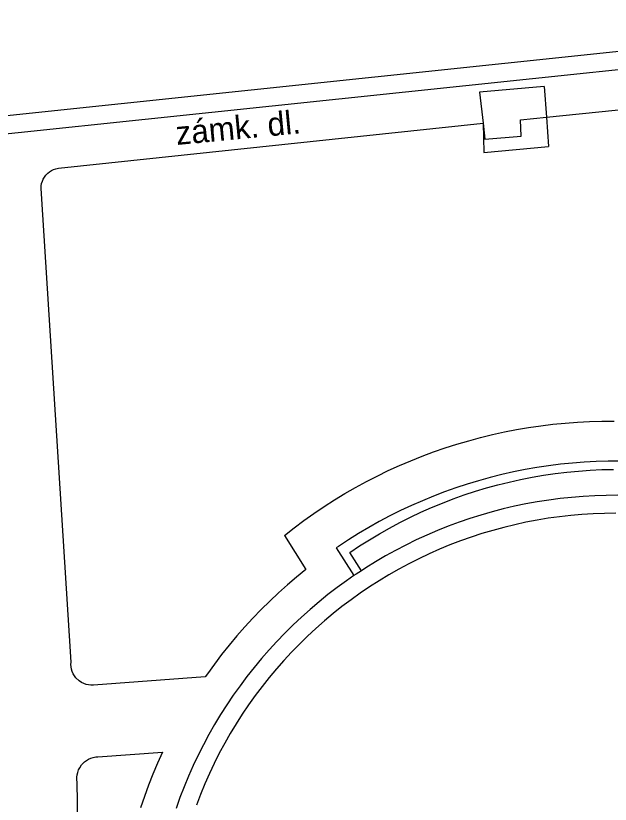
# Model space of a CAD drawing. Extents: x -539515 to -538098, y -1182060 to -1180157.
# Drawn here: x -539326.9 to -539310.4, y -1181191.92 to -1181170.02 of the extents above; entities that cross this region are included whole.
import ezdxf

# ---------------------------------------------------------------- set-up
doc = ezdxf.new("R2010")
doc.units = 0
for name, color, linetype in [('Vrstva 11', 7, 'Continuous'), ('Vrstva 40', 7, 'Continuous'), ('Vrstva 5', 7, 'Continuous')]:
    doc.layers.add(name, color=color, linetype=linetype)

msp = doc.modelspace()

# ---------------------------------------------------------------- linework, layer by layer
at = {"layer": 'Vrstva 11'}
for p, q in [((-539312.23, -1181171.98), (-539314.02, -1181172.14)), ((-539312.23, -1181171.98), (-539312.168, -1181172.836)), ((-539312.87, -1181173.36), (-539312.89, -1181172.91)), ((-539312.168, -1181172.836), (-539312.11, -1181173.65)), ((-539325.71, -1181174.25), (-539313.92, -1181173)), ((-539313.88, -1181173.44), (-539312.87, -1181173.36)), ((-539313.9, -1181173.81), (-539312.11, -1181173.65)), ((-539325.36, -1181187.97), (-539326.19, -1181174.81)), ((-539319.44, -1181184.45), (-539318.844, -1181185.399)), ((-539318, -1181184.8), (-539317.51, -1181185.57)), ((-539317.302, -1181185.432), (-539317.623, -1181184.926)), ((-539321.635, -1181188.38), (-539324.74, -1181188.61)), ((-539324.62, -1181190.6), (-539322.827, -1181190.472)), ((-539325.16, -1181193.67), (-539325.19, -1181191.31))]:
    msp.add_line(p, q, dxfattribs=at)
for points in [[(-539312.168, -1181172.836), (-539303.54, -1181171.95)], [(-539314.02, -1181172.14), (-539313.92, -1181173), (-539313.9, -1181173.81)], [(-539312.89, -1181172.91), (-539312.168, -1181172.836)], [(-539313.92, -1181173), (-539313.88, -1181173.44)], [(-539326.19, -1181174.81), (-539326.187, -1181174.744), (-539326.177, -1181174.678), (-539326.158, -1181174.614), (-539326.133, -1181174.553), (-539326.099, -1181174.495), (-539326.06, -1181174.442), (-539326.01, -1181174.39), (-539325.962, -1181174.351), (-539325.906, -1181174.315), (-539325.847, -1181174.286), (-539325.784, -1181174.265), (-539325.71, -1181174.25)], [(-539319.44, -1181184.45), (-539319.172, -1181184.24), (-539318.898, -1181184.037), (-539318.62, -1181183.841), (-539318.338, -1181183.65), (-539318.051, -1181183.467), (-539317.759, -1181183.29), (-539317.464, -1181183.121), (-539317.165, -1181182.958), (-539316.862, -1181182.802), (-539316.556, -1181182.653), (-539316.246, -1181182.512), (-539315.933, -1181182.378), (-539315.617, -1181182.252), (-539315.298, -1181182.132), (-539314.976, -1181182.021), (-539314.651, -1181181.917), (-539314.325, -1181181.82), (-539313.996, -1181181.732), (-539313.665, -1181181.651), (-539313.333, -1181181.578), (-539312.998, -1181181.512), (-539312.663, -1181181.455), (-539312.326, -1181181.405), (-539311.988, -1181181.364), (-539311.649, -1181181.33), (-539311.309, -1181181.304), (-539310.969, -1181181.287), (-539310.629, -1181181.277), (-539310.288, -1181181.275)], [(-539310.121, -1181182.386), (-539310.453, -1181182.388), (-539310.785, -1181182.397), (-539311.116, -1181182.415), (-539311.447, -1181182.441), (-539311.776, -1181182.474), (-539312.106, -1181182.516), (-539312.434, -1181182.566), (-539312.76, -1181182.623), (-539313.085, -1181182.688), (-539313.409, -1181182.761), (-539313.731, -1181182.842), (-539314.05, -1181182.931), (-539314.368, -1181183.027), (-539314.683, -1181183.131), (-539314.995, -1181183.242)], [(-539317.623, -1181184.926), (-539317.353, -1181184.746), (-539317.079, -1181184.572), (-539316.801, -1181184.405), (-539316.519, -1181184.246), (-539316.233, -1181184.093), (-539315.943, -1181183.947), (-539315.65, -1181183.808), (-539315.353, -1181183.677), (-539315.054, -1181183.553), (-539314.751, -1181183.437), (-539314.446, -1181183.328), (-539314.138, -1181183.226), (-539313.827, -1181183.133), (-539313.514, -1181183.046), (-539313.2, -1181182.968), (-539312.883, -1181182.897), (-539312.565, -1181182.835), (-539312.245, -1181182.78), (-539311.924, -1181182.733), (-539311.602, -1181182.694), (-539311.28, -1181182.663), (-539310.956, -1181182.639), (-539310.632, -1181182.624), (-539310.308, -1181182.617)], [(-539314.995, -1181183.242), (-539315.305, -1181183.361), (-539315.611, -1181183.488), (-539315.915, -1181183.622), (-539316.215, -1181183.763), (-539316.512, -1181183.911), (-539316.805, -1181184.066), (-539317.094, -1181184.229), (-539317.379, -1181184.398), (-539317.66, -1181184.574), (-539317.937, -1181184.757), (-539318, -1181184.8)], [(-539318.844, -1181185.399), (-539319.102, -1181185.609), (-539319.356, -1181185.825), (-539319.604, -1181186.048), (-539319.847, -1181186.276), (-539320.084, -1181186.51), (-539320.315, -1181186.75), (-539320.541, -1181186.995), (-539320.761, -1181187.245), (-539320.974, -1181187.501), (-539321.182, -1181187.762), (-539321.383, -1181188.027), (-539321.578, -1181188.298), (-539321.635, -1181188.38)], [(-539324.74, -1181188.61), (-539324.808, -1181188.611), (-539324.876, -1181188.605), (-539324.942, -1181188.59), (-539325.006, -1181188.568), (-539325.068, -1181188.538), (-539325.14, -1181188.49), (-539325.225, -1181188.409), (-539325.266, -1181188.355), (-539325.3, -1181188.297), (-539325.327, -1181188.234), (-539325.347, -1181188.169), (-539325.359, -1181188.102), (-539325.363, -1181188.034), (-539325.36, -1181187.97)], [(-539325.19, -1181191.31), (-539325.198, -1181191.241), (-539325.199, -1181191.172), (-539325.191, -1181191.102), (-539325.175, -1181191.035), (-539325.152, -1181190.969), (-539325.121, -1181190.907), (-539325.07, -1181190.83), (-539324.99, -1181190.746), (-539324.935, -1181190.704), (-539324.875, -1181190.668), (-539324.812, -1181190.64), (-539324.746, -1181190.619), (-539324.677, -1181190.605), (-539324.62, -1181190.6)], [(-539322.827, -1181190.472), (-539322.962, -1181190.776), (-539323.091, -1181191.084), (-539323.212, -1181191.394), (-539323.325, -1181191.708), (-539323.431, -1181192.024)]]:
    msp.add_lwpolyline(points, dxfattribs=at)
at = {"layer": 'Vrstva 5'}
for p, q in [((-539331.77, -1181173.271), (-539300.782, -1181170.015)), ((-539311.786, -1181183.428), (-539312.104, -1181183.47)), ((-539311.467, -1181183.394), (-539311.786, -1181183.428)), ((-539311.147, -1181183.368), (-539311.467, -1181183.394)), ((-539310.826, -1181183.349), (-539311.147, -1181183.368)), ((-539310.505, -1181183.339), (-539310.826, -1181183.349)), ((-539310.184, -1181183.337), (-539310.505, -1181183.339)), ((-539313.051, -1181183.643), (-539313.364, -1181183.716)), ((-539312.737, -1181183.577), (-539313.051, -1181183.643)), ((-539312.421, -1181183.519), (-539312.737, -1181183.577)), ((-539312.104, -1181183.47), (-539312.421, -1181183.519)), ((-539313.674, -1181183.797), (-539313.983, -1181183.886)), ((-539313.364, -1181183.716), (-539313.674, -1181183.797)), ((-539311.18, -1181183.871), (-539311.493, -1181183.899)), ((-539310.866, -1181183.852), (-539311.18, -1181183.871)), ((-539310.551, -1181183.84), (-539310.866, -1181183.852)), ((-539310.236, -1181183.837), (-539310.551, -1181183.84)), ((-539314.593, -1181184.087), (-539314.894, -1181184.199)), ((-539314.289, -1181183.983), (-539314.593, -1181184.087)), ((-539313.983, -1181183.886), (-539314.289, -1181183.983)), ((-539312.737, -1181184.087), (-539313.045, -1181184.154)), ((-539312.428, -1181184.028), (-539312.737, -1181184.087)), ((-539312.118, -1181183.977), (-539312.428, -1181184.028)), ((-539311.806, -1181183.934), (-539312.118, -1181183.977)), ((-539311.493, -1181183.899), (-539311.806, -1181183.934)), ((-539315.192, -1181184.318), (-539315.487, -1181184.445)), ((-539314.894, -1181184.199), (-539315.192, -1181184.318)), ((-539313.655, -1181184.311), (-539313.956, -1181184.401)), ((-539313.351, -1181184.229), (-539313.655, -1181184.311)), ((-539313.045, -1181184.154), (-539313.351, -1181184.229)), ((-539315.487, -1181184.445), (-539315.779, -1181184.578)), ((-539314.255, -1181184.499), (-539314.552, -1181184.604)), ((-539313.956, -1181184.401), (-539314.255, -1181184.499)), ((-539316.067, -1181184.72), (-539316.352, -1181184.868)), ((-539315.779, -1181184.578), (-539316.067, -1181184.72)), ((-539314.846, -1181184.717), (-539315.137, -1181184.837)), ((-539314.552, -1181184.604), (-539314.846, -1181184.717)), ((-539316.352, -1181184.868), (-539316.633, -1181185.023)), ((-539315.424, -1181184.965), (-539315.709, -1181185.1)), ((-539315.137, -1181184.837), (-539315.424, -1181184.965)), ((-539316.91, -1181185.185), (-539317.183, -1181185.354)), ((-539316.633, -1181185.023), (-539316.91, -1181185.185)), ((-539315.709, -1181185.1), (-539315.99, -1181185.242)), ((-539317.183, -1181185.354), (-539317.302, -1181185.432)), ((-539316.267, -1181185.391), (-539316.54, -1181185.547)), ((-539315.99, -1181185.242), (-539316.267, -1181185.391)), ((-539317.51, -1181185.57), (-539317.715, -1181185.713)), ((-539317.451, -1181185.53), (-539317.51, -1181185.57)), ((-539317.302, -1181185.432), (-539317.451, -1181185.53)), ((-539316.54, -1181185.547), (-539316.809, -1181185.71)), ((-539317.715, -1181185.713), (-539317.975, -1181185.902)), ((-539316.809, -1181185.71), (-539317.074, -1181185.88)), ((-539317.975, -1181185.902), (-539318.23, -1181186.097)), ((-539317.335, -1181186.056), (-539317.591, -1181186.24)), ((-539317.074, -1181185.88), (-539317.335, -1181186.056)), ((-539318.23, -1181186.097), (-539318.479, -1181186.299)), ((-539317.591, -1181186.24), (-539317.842, -1181186.429)), ((-539318.724, -1181186.507), (-539318.963, -1181186.721)), ((-539318.479, -1181186.299), (-539318.724, -1181186.507)), ((-539317.842, -1181186.429), (-539318.089, -1181186.625)), ((-539318.963, -1181186.721), (-539319.197, -1181186.94)), ((-539318.089, -1181186.625), (-539318.33, -1181186.827)), ((-539319.197, -1181186.94), (-539319.426, -1181187.166)), ((-539318.33, -1181186.827), (-539318.566, -1181187.035)), ((-539319.426, -1181187.166), (-539319.649, -1181187.397)), ((-539318.566, -1181187.035), (-539318.797, -1181187.249)), ((-539318.797, -1181187.249), (-539319.022, -1181187.469)), ((-539319.649, -1181187.397), (-539319.866, -1181187.634)), ((-539319.022, -1181187.469), (-539319.242, -1181187.694)), ((-539319.866, -1181187.634), (-539320.077, -1181187.876)), ((-539319.242, -1181187.694), (-539319.455, -1181187.925)), ((-539320.077, -1181187.876), (-539320.281, -1181188.123)), ((-539319.455, -1181187.925), (-539319.663, -1181188.162)), ((-539320.281, -1181188.123), (-539320.48, -1181188.375)), ((-539319.663, -1181188.162), (-539319.865, -1181188.403)), ((-539320.48, -1181188.375), (-539320.672, -1181188.632)), ((-539319.865, -1181188.403), (-539320.061, -1181188.65)), ((-539320.672, -1181188.632), (-539320.858, -1181188.894)), ((-539320.061, -1181188.65), (-539320.25, -1181188.901)), ((-539320.858, -1181188.894), (-539321.037, -1181189.16)), ((-539320.25, -1181188.901), (-539320.433, -1181189.158)), ((-539321.037, -1181189.16), (-539321.21, -1181189.431)), ((-539320.433, -1181189.158), (-539320.609, -1181189.418)), ((-539321.21, -1181189.431), (-539321.376, -1181189.706)), ((-539320.609, -1181189.418), (-539320.778, -1181189.684)), ((-539321.376, -1181189.706), (-539321.535, -1181189.985)), ((-539320.778, -1181189.684), (-539320.941, -1181189.953)), ((-539321.535, -1181189.985), (-539321.687, -1181190.268)), ((-539320.941, -1181189.953), (-539321.097, -1181190.227)), ((-539321.097, -1181190.227), (-539321.246, -1181190.504)), ((-539321.687, -1181190.268), (-539321.831, -1181190.554)), ((-539321.831, -1181190.554), (-539321.969, -1181190.844)), ((-539321.246, -1181190.504), (-539321.388, -1181190.785)), ((-539321.969, -1181190.844), (-539322.099, -1181191.138)), ((-539321.388, -1181190.785), (-539321.522, -1181191.069)), ((-539321.522, -1181191.069), (-539321.649, -1181191.357)), ((-539322.099, -1181191.138), (-539322.222, -1181191.434)), ((-539322.222, -1181191.434), (-539322.338, -1181191.734)), ((-539321.649, -1181191.357), (-539321.769, -1181191.648)), ((-539322.338, -1181191.734), (-539322.446, -1181192.036)), ((-539321.769, -1181191.648), (-539321.882, -1181191.942))]:
    msp.add_line(p, q, dxfattribs=at)
msp.add_lwpolyline([(-539332.21, -1181173.82), (-539303.652, -1181170.82)], dxfattribs=at)

# ---------------------------------------------------------------- texts
at = {"layer": 'Vrstva 40'}
msp.add_text('zámk. dl.', height=0.65, rotation=5.4216, dxfattribs=at).set_placement((-539322.428, -1181173.606))

doc.saveas('drawing.dxf')
